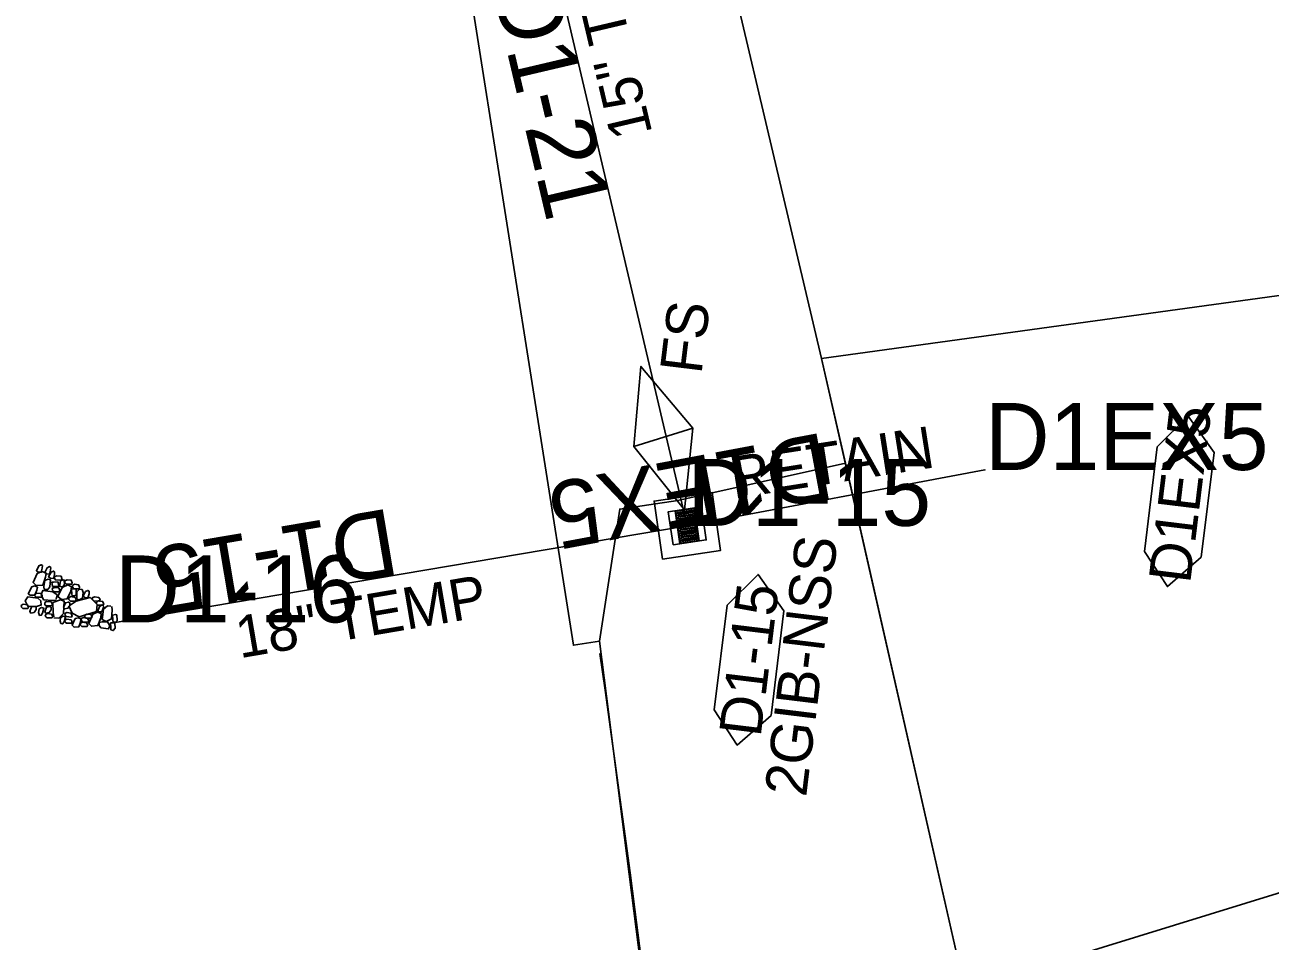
# Model space of a CAD drawing. Extents: x 465700 to 483515, y 488970 to 507540.
# Drawn here: x 481260.3 to 481409.1, y 491733.6 to 491843.1 of the extents above; entities that cross this region are included whole.
import ezdxf

# ---------------------------------------------------------------- set-up
doc = ezdxf.new("R2010")
doc.units = 0
for name, color, linetype in [('Default', 7, 'Continuous'), ('Exist Plan Preparation Watershed Blue', 7, 'Continuous'), ('Prop Drainage Structure Box Number Symbol CELL', 7, 'Continuous'), ('Prop Drainage Structure Drop Inlet Grate 2 Narrow Slots and Sag Grates 840 24 CELL', 7, 'Continuous'), ('Prop Drainage Structure Junction Box with Manhole Label', 7, 'Continuous'), ('Prop Drainage Structure Pipe Collar Label', 7, 'Continuous'), ('Prop Drainage Structure Pipe RCP 15in Class III', 7, 'Continuous'), ('Prop Drainage Structure Pipe RCP 15in Class III Label', 7, 'Continuous'), ('Prop Drainage Structure Pipe RCP 18in Class III', 7, 'Continuous'), ('Prop Drainage Structure Pipe RCP 18in Class III Label', 7, 'Continuous'), ('Prop Drainage Structure Pipe Stub Out CELL', 7, 'Continuous'), ('Prop Drainage Structure Plot Symbol 20 Scale CELL', 7, 'Continuous'), ('Prop Drainage Structure Plot Symbol 50 Scale CELL', 7, 'Continuous'), ('Prop Earthen Structure False Sump CELL', 7, 'Continuous'), ('Prop Earthen Structure False Sump Label', 7, 'Continuous'), ('Prop Erosion Rip Rap Pad at Outlet CELL', 7, 'Continuous'), ('Scratch_Level_8', 7, 'Continuous')]:
    doc.layers.add(name, color=color, linetype=linetype)

msp = doc.modelspace()

# ---------------------------------------------------------------- linework, layer by layer
at = {"layer": 'Default'}
msp.add_arc((478448.2, 491360.26), 2909.5, 356.95228, 8.055, dxfattribs=at)
at = {"layer": 'Exist Plan Preparation Watershed Blue'}
for points in [[(481914.1, 492508.16), (481856.26, 492637.66), (481730.25, 492750.66), (481730.25, 492750.66), (481669.43, 492692.33), (481584.65, 492614.4), (481584.65, 492614.4), (481584.65, 492614.4), (481329.7, 492355.65), (481209.8, 492230.86), (481241.6, 492138.31), (481300.91, 491917.87), (481327.1, 491923.15), (481339.19, 491872.39), (481355.48, 491803.22), (481355.48, 491803.22), (481355.48, 491803.22)], [(481355.48, 491803.22), (481621.38, 491839.87), (481663.65, 491819.01), (481786.78, 491759.9), (481848.66, 491780.37), (481859.12, 491782.21), (481859.12, 491782.21), (481859.12, 491782.21), (482127.99, 491863.91)], [(481351.25, 491164.11), (481355.63, 491237.92), (481357.02, 491295.88), (481357.71, 491377.55), (481356.61, 491435.42), (481354.34, 491495.85), (481349.13, 491584.55), (481341.19, 491673.05), (481328.95, 491769.45), (481331.36, 491785.24), (481338.28, 491786.26), (481358.32, 491790.73), (481372.6, 491727.76), (481383.56, 491677.38), (481390.7, 491636.27), (481400.08, 491578.77), (481407.45, 491514.97), (481410.05, 491479.29), (481411.52, 491442.54), (481412.58, 491412.05), (481413.67, 491377.22), (481412.27, 491323.04), (481409.74, 491273.14), (481400.35, 491179.93)], [(481400.08, 491578.77), (481390.7, 491636.27), (481383.56, 491677.38), (481376.93, 491707.39), (481374.23, 491721.13), (481372.6, 491727.76), (481418.44, 491741.89), (481486.66, 491760.25), (481538.81, 491759.7), (481786.78, 491759.9), (481786.78, 491759.9), (481786.78, 491759.9), (481786.78, 491759.9), (481786.78, 491759.9), (481786.78, 491759.9), (481786.78, 491759.9), (481786.78, 491759.9), (481786.78, 491759.9), (481568.07, 491531.08)]]:
    msp.add_lwpolyline(points, dxfattribs=at)
for points in [[(481328.95, 491769.45), (481325.82, 491768.95), (481313.54, 491846.95), (481303.37, 491904.07), (481300.91, 491917.87), (481304.12, 491918.69), (481311, 491920.02), (481327.1, 491923.15), (481339.19, 491872.39), (481355.48, 491803.22), (481358.32, 491790.73), (481338.28, 491786.26), (481331.36, 491785.24)], [(481372.6, 491727.76), (481418.44, 491741.89), (481486.66, 491760.25), (481538.81, 491759.7), (481786.78, 491759.9), (481720.28, 491792.68), (481663.65, 491819.01), (481642.72, 491828.88), (481621.38, 491839.87), (481355.48, 491803.22)]]:
    msp.add_lwpolyline(points, close=True, dxfattribs=at)
at = {"layer": 'Prop Drainage Structure Box Number Symbol CELL'}
for points in [[(481394.05, 491780.17), (481395.57, 491792.68), (481399.28, 491796.36), (481402.36, 491792.01), (481400.83, 491779.5), (481396.79, 491775.97), (481394.05, 491780.17)], [(481342.65, 491761.22), (481344.18, 491773.74), (481347.88, 491777.42), (481350.96, 491773.07), (481349.43, 491760.56), (481345.39, 491757.02), (481342.65, 491761.22)]]:
    msp.add_lwpolyline(points, dxfattribs=at)
at = {"layer": 'Prop Drainage Structure Drop Inlet Grate 2 Narrow Slots and Sag Grates 840 24 CELL'}
for p, q in [((481339.13, 491785.21), (481339.13, 491785.21)), ((481338.27, 491783.06), (481338.27, 491783.06)), ((481339.42, 491783.23), (481339.42, 491783.23)), ((481340.57, 491783.4), (481340.57, 491783.4)), ((481339.71, 491781.25), (481339.71, 491781.25))]:
    msp.add_line(p, q, dxfattribs=at)
for points in [[(481338.55, 491781.08), (481337.98, 491785.04), (481340.28, 491785.38), (481340.86, 491781.42), (481338.55, 491781.08)], [(481338.61, 491781.15), (481338.05, 491784.99), (481340.23, 491785.31), (481340.79, 491781.47), (481338.61, 491781.15)], [(481338.34, 491783.08), (481338.06, 491784.98), (481340.22, 491785.3), (481340.5, 491783.4), (481338.34, 491783.08)], [(481338.29, 491784.67), (481338.26, 491784.84), (481340.07, 491785.1), (481340.09, 491784.93), (481338.29, 491784.67)], [(481338.33, 491784.37), (481338.31, 491784.55), (481340.11, 491784.81), (481340.14, 491784.64), (481338.33, 491784.37)], [(481338.37, 491784.08), (481338.35, 491784.25), (481340.15, 491784.52), (481340.18, 491784.34), (481338.37, 491784.08)], [(481338.62, 491781.17), (481338.34, 491783.06), (481340.5, 491783.38), (481340.78, 491781.48), (481338.62, 491781.17)], [(481338.42, 491783.78), (481338.39, 491783.96), (481340.2, 491784.22), (481340.22, 491784.05), (481338.42, 491783.78)], [(481338.46, 491783.49), (481338.43, 491783.67), (481340.24, 491783.93), (481340.26, 491783.75), (481338.46, 491783.49)], [(481338.5, 491783.2), (481338.48, 491783.37), (481340.28, 491783.64), (481340.31, 491783.46), (481338.5, 491783.2)], [(481338.56, 491782.83), (481338.53, 491783), (481340.34, 491783.26), (481340.36, 491783.09), (481338.56, 491782.83)], [(481338.6, 491782.53), (481338.58, 491782.71), (481340.38, 491782.97), (481340.4, 491782.8), (481338.6, 491782.53)], [(481338.64, 491782.24), (481338.62, 491782.41), (481340.42, 491782.68), (481340.45, 491782.5), (481338.64, 491782.24)], [(481338.69, 491781.94), (481338.66, 491782.12), (481340.46, 491782.38), (481340.49, 491782.21), (481338.69, 491781.94)], [(481338.73, 491781.65), (481338.7, 491781.83), (481340.51, 491782.09), (481340.53, 491781.91), (481338.73, 491781.65)], [(481338.77, 491781.36), (481338.75, 491781.53), (481340.55, 491781.8), (481340.58, 491781.62), (481338.77, 491781.36)]]:
    msp.add_lwpolyline(points, dxfattribs=at)
at = {"layer": 'Prop Drainage Structure Pipe RCP 15in Class III'}
msp.add_line((481308.23, 491915.92), (481339.42, 491783.23), dxfattribs=at)
at = {"layer": 'Prop Drainage Structure Pipe RCP 18in Class III'}
msp.add_line((481339.42, 491783.23), (481271.07, 491771.69), dxfattribs=at)
at = {"layer": 'Prop Drainage Structure Pipe Stub Out CELL'}
msp.add_line((481374.98, 491789.91), (481374.98, 491789.91), dxfattribs=at)
msp.add_line((481374.98, 491789.91), (481374.98, 491789.91), dxfattribs=at)
msp.add_lwpolyline([(481374.96, 491789.9), (481374.98, 491789.92), (481375, 491789.91), (481374.98, 491789.89), (481374.96, 491789.9)], dxfattribs=at)
at = {"layer": 'Prop Drainage Structure Plot Symbol 20 Scale CELL'}
msp.add_lwpolyline([(481337.73, 491780.96), (481337.15, 491784.92), (481341.11, 491785.5), (481341.69, 491781.54)], close=True, dxfattribs=at)
at = {"layer": 'Prop Drainage Structure Plot Symbol 50 Scale CELL'}
msp.add_lwpolyline([(481336.46, 491779.26), (481335.45, 491786.19), (481342.38, 491787.2), (481343.39, 491780.27)], close=True, dxfattribs=at)
at = {"layer": 'Prop Earthen Structure False Sump CELL'}
msp.add_lwpolyline([(481339.11, 491785.14), (481333.04, 491792.71), (481333.89, 491802.29), (481340.07, 491794.92), (481333.04, 491792.71), (481340.07, 491794.92), (481339.11, 491785.14)], dxfattribs=at)
at = {"layer": 'Prop Erosion Rip Rap Pad at Outlet CELL'}
msp.add_line((481271.07, 491771.69), (481271.07, 491771.69), dxfattribs=at)
msp.add_line((481271.07, 491771.69), (481271.07, 491771.69), dxfattribs=at)
for points in [[(481262.4, 491778.48), (481262.37, 491778.16), (481262.24, 491777.69), (481261.88, 491777.71), (481261.66, 491777.87), (481261.95, 491778.44), (481262.23, 491778.57), (481262.4, 491778.48)], [(481262.84, 491777.59), (481262.73, 491777.08), (481262.42, 491776.15), (481261.63, 491776.08), (481261.26, 491776.45), (481261.75, 491777.55), (481262.35, 491777.77), (481262.84, 491777.59)], [(481263.39, 491778.26), (481263.36, 491777.95), (481263.23, 491777.47), (481262.87, 491777.49), (481262.65, 491777.65), (481262.94, 491778.22), (481263.22, 491778.35), (481263.39, 491778.26)], [(481263.84, 491777.74), (481263.82, 491777.42), (481263.69, 491776.95), (481263.34, 491776.97), (481263.11, 491777.13), (481263.41, 491777.7), (481263.69, 491777.83), (481263.84, 491777.74)], [(481263.8, 491777.15), (481264.11, 491777.24), (481264.62, 491777.2), (481264.71, 491776.92), (481264.65, 491776.76), (481264, 491776.75), (481263.83, 491776.94), (481263.8, 491777.15)], [(481261.78, 491775.9), (481261.71, 491775.53), (481261.49, 491774.94), (481260.92, 491774.93), (481260.68, 491775.11), (481261.11, 491775.95), (481261.48, 491776.06), (481261.78, 491775.9)], [(481262.58, 491775.61), (481262.53, 491775.99), (481262.66, 491776.7), (481263.05, 491776.87), (481263.33, 491776.76), (481263.25, 491775.92), (481263.02, 491775.61), (481262.58, 491775.61)], [(481263.51, 491776.5), (481263.71, 491776.5), (481264.24, 491776.52), (481264.35, 491776.15), (481264.28, 491775.98), (481263.6, 491775.99), (481263.53, 491776.25), (481263.51, 491776.5)], [(481263.55, 491775.73), (481263.84, 491775.87), (481264.33, 491775.8), (481264.46, 491775.5), (481264.37, 491775.34), (481263.77, 491775.36), (481263.59, 491775.51), (481263.55, 491775.73)], [(481265.87, 491775.95), (481265.78, 491775.42), (481265.34, 491774.51), (481264.67, 491774.44), (481264.24, 491774.78), (481264.75, 491775.87), (481265.4, 491776.19), (481265.87, 491775.95)], [(481264.47, 491775.93), (481264.48, 491776.16), (481264.55, 491776.65), (481264.83, 491776.78), (481264.98, 491776.74), (481265.02, 491776.2), (481264.8, 491775.96), (481264.59, 491775.92)], [(481265.07, 491776.64), (481265.32, 491776.79), (481265.82, 491776.72), (481265.95, 491776.43), (481265.88, 491776.26), (481265.24, 491776.25), (481265.07, 491776.44), (481265.07, 491776.64)], [(481265.92, 491774.87), (481265.89, 491775.11), (481265.87, 491775.64), (481266.25, 491775.71), (481266.4, 491775.65), (481266.4, 491775), (481266.24, 491774.86), (481265.92, 491774.87)], [(481265.96, 491776.09), (481266.2, 491776.24), (481266.7, 491776.17), (481266.83, 491775.88), (481266.76, 491775.7), (481266.13, 491775.7), (481265.96, 491775.89), (481265.96, 491776.09)], [(481267.13, 491775.62), (481267.23, 491775.27), (481267.18, 491774.57), (481266.78, 491774.37), (481266.5, 491774.48), (481266.5, 491775.35), (481266.81, 491775.64), (481267.13, 491775.62)], [(481262.16, 491773.73), (481261.68, 491773.58), (481260.65, 491773.64), (481260.33, 491774.28), (481260.63, 491774.73), (481261.85, 491774.6), (481262.2, 491774.26), (481262.23, 491773.7)], [(481261.47, 491775.06), (481261.73, 491775.2), (481262.23, 491775.15), (481262.36, 491774.86), (481262.29, 491774.69), (481261.64, 491774.69), (481261.47, 491774.86), (481261.47, 491775.06)], [(481264.02, 491774.34), (481263.58, 491774.32), (481262.52, 491774.39), (481262.25, 491775.01), (481262.43, 491775.5), (481263.64, 491775.33), (481264.16, 491774.98), (481264.03, 491774.46)], [(481262.66, 491774.05), (481262.88, 491774.17), (481263.44, 491774.13), (481263.57, 491773.84), (481263.46, 491773.68), (481262.83, 491773.68), (481262.68, 491773.8), (481262.66, 491774.05)], [(481263.76, 491772.34), (481263.68, 491772.87), (481263.64, 491774.05), (481264.53, 491774.4), (481264.99, 491774.23), (481264.88, 491772.75), (481264.36, 491772.19), (481263.73, 491772.22)], [(481265.67, 491774.04), (481265.67, 491773.72), (481265.43, 491773.37), (481265.04, 491773.31), (481264.91, 491773.48), (481265.12, 491774.04), (481265.49, 491774.11), (481265.67, 491774.04)], [(481265.69, 491773.73), (481266.4, 491774.22), (481268.07, 491774.68), (481268.91, 491773.81), (481268.85, 491772.99), (481266.79, 491772.36), (481265.92, 491772.81), (481265.53, 491773.68)], [(481265.55, 491774.63), (481265.78, 491774.77), (481266.28, 491774.67), (481266.42, 491774.43), (481266.34, 491774.22), (481265.72, 491774.24), (481265.55, 491774.42), (481265.55, 491774.63)], [(481267.98, 491775.42), (481267.95, 491775.11), (481267.81, 491774.64), (481267.46, 491774.66), (481267.24, 491774.81), (481267.53, 491775.38), (481267.81, 491775.51), (481267.98, 491775.42)], [(481268.34, 491774.64), (481268.62, 491774.75), (481269.12, 491774.68), (481269.26, 491774.43), (481269.18, 491774.22), (481268.53, 491774.26), (481268.38, 491774.43), (481268.34, 491774.64)], [(481268.83, 491774.11), (481269.08, 491774.26), (481269.57, 491774.19), (481269.7, 491773.9), (481269.63, 491773.73), (481269, 491773.74), (481268.83, 491773.91), (481268.83, 491774.11)], [(481259.85, 491773.72), (481260.1, 491773.88), (481260.59, 491773.8), (481260.73, 491773.52), (481260.63, 491773.35), (481260.04, 491773.36), (481259.89, 491773.5), (481259.85, 491773.72)], [(481261.64, 491773.53), (481261.64, 491773.21), (481261.39, 491772.86), (481261.01, 491772.81), (481260.87, 491772.99), (481261.08, 491773.55), (481261.47, 491773.6), (481261.64, 491773.53)], [(481262.04, 491772.53), (481261.92, 491772.85), (481262, 491773.29), (481262.27, 491773.48), (481262.55, 491773.38), (481262.41, 491772.79), (481262.24, 491772.54), (481262.04, 491772.53)], [(481263.43, 491773.52), (481263.43, 491773.19), (481263.19, 491772.85), (481262.8, 491772.79), (481262.67, 491772.96), (481262.88, 491773.52), (481263.25, 491773.59), (481263.43, 491773.52)], [(481262.72, 491772.59), (481262.97, 491772.75), (481263.47, 491772.67), (481263.61, 491772.4), (481263.51, 491772.24), (481262.92, 491772.24), (481262.77, 491772.37), (481262.72, 491772.59)], [(481265.05, 491772.77), (481265.3, 491772.88), (481265.77, 491772.79), (481265.92, 491772.53), (481265.84, 491772.32), (481265.22, 491772.38), (481265.09, 491772.55), (481265.05, 491772.77)], [(481267.43, 491772.55), (481267.67, 491772.69), (481268.17, 491772.62), (481268.31, 491772.34), (481268.21, 491772.18), (481267.61, 491772.19), (481267.46, 491772.33), (481267.43, 491772.55)], [(481269.41, 491772.75), (481269.34, 491772.25), (481268.99, 491771.3), (481268.23, 491771.22), (481267.91, 491771.54), (481268.42, 491772.68), (481268.95, 491772.91), (481269.41, 491772.75)], [(481269.71, 491773.6), (481269.64, 491773.39), (481269.49, 491772.96), (481269.16, 491772.96), (481268.99, 491773.03), (481269.2, 491773.59), (481269.51, 491773.79), (481269.71, 491773.6)], [(481270.68, 491773.59), (481270.71, 491773.15), (481270.65, 491772.12), (481270.01, 491771.8), (481269.52, 491772.03), (481269.67, 491773.25), (481270.15, 491773.68), (481270.56, 491773.64)], [(481270.79, 491771.8), (481270.8, 491772.03), (481270.76, 491772.57), (481271.1, 491772.65), (481271.27, 491772.58), (481271.32, 491771.91), (481271.07, 491771.69), (481270.79, 491771.8)], [(481264.6, 491771.57), (481264.5, 491771.82), (481264.53, 491772.24), (481264.82, 491772.45), (481265.13, 491772.35), (481264.98, 491771.76), (481264.78, 491771.51), (481264.6, 491771.57)], [(481265.05, 491771.95), (481265.3, 491772.09), (481265.8, 491772.01), (481265.93, 491771.74), (481265.83, 491771.58), (481265.24, 491771.59), (481265.09, 491771.73), (481265.05, 491771.95)], [(481266.96, 491772.13), (481266.93, 491771.71), (481266.72, 491771.15), (481266.16, 491771.11), (481265.92, 491771.37), (481266.31, 491772.14), (481266.69, 491772.23), (481266.96, 491772.13)], [(481266.91, 491771.55), (481267.16, 491771.71), (481267.65, 491771.63), (481267.8, 491771.35), (481267.69, 491771.19), (481267.1, 491771.21), (481266.94, 491771.34), (481266.91, 491771.55)], [(481266.99, 491772.14), (481267.29, 491772.27), (481267.76, 491772.16), (481267.91, 491771.91), (481267.83, 491771.7), (481267.16, 491771.75), (481267.03, 491771.92), (481266.99, 491772.14)], [(481269.17, 491771.69), (481269.52, 491771.75), (481270.15, 491771.76), (481270.42, 491771.29), (481270.29, 491770.91), (481269.37, 491771.05), (481269.16, 491771.33), (481269.17, 491771.69)], [(481270.55, 491770.8), (481270.55, 491771.05), (481270.53, 491771.62), (481270.86, 491771.65), (481271.04, 491771.59), (481271.07, 491770.98), (481270.84, 491770.7), (481270.55, 491770.8)]]:
    msp.add_lwpolyline(points, dxfattribs=at)
at = {"layer": 'Scratch_Level_8'}
for p, q in [((481308.23, 491915.92), (481339.42, 491783.23)), ((481374.98, 491789.91), (481339.42, 491783.23)), ((481339.42, 491783.23), (481271.07, 491771.69))]:
    msp.add_line(p, q, dxfattribs=at)

# ---------------------------------------------------------------- texts
at = {"layer": 'Prop Drainage Structure Box Number Symbol CELL'}
for s, p in [('D1EX5', (481399.5, 491776.24)), ('D1-15', (481348.18, 491757.89))]:
    msp.add_text(s, height=5, rotation=83.0394, dxfattribs=at).set_placement(p)
at = {"layer": 'Prop Drainage Structure Junction Box with Manhole Label'}
msp.add_text('2GIB-NSS', height=5, rotation=83.0365, dxfattribs=at).set_placement((481353.62, 491750.73))
at = {"layer": 'Prop Drainage Structure Pipe Collar Label'}
msp.add_text('RETAIN', height=5, rotation=8.9195, dxfattribs=at).set_placement((481344.96, 491786.45))
at = {"layer": 'Prop Drainage Structure Pipe RCP 15in Class III Label'}
msp.add_text('15" TEMP', height=5, rotation=103.2285, dxfattribs=at).set_placement((481335.27, 491830.17))
at = {"layer": 'Prop Drainage Structure Pipe RCP 18in Class III Label'}
msp.add_text('18" TEMP', height=5, rotation=9.7092, dxfattribs=at).set_placement((481285.95, 491767.39))
at = {"layer": 'Prop Drainage Structure Pipe Stub Out CELL'}
msp.add_text('SO', height=0.0104, rotation=12.9811, dxfattribs=at).set_placement((481374.97, 491789.9))
at = {"layer": 'Prop Earthen Structure False Sump Label'}
msp.add_text('FS', height=5, rotation=83.0423, dxfattribs=at).set_placement((481341.11, 491801.27))
at = {"layer": 'Scratch_Level_8'}
for s, rotation, p in [('D1-21', 283.2285, (481316.04, 491847.75)), ('D1EX5', 190.632, (481355.72, 491794.43)), ('D1-15', 189.5858, (481303.91, 491785.35))]:
    msp.add_text(s, height=8, rotation=rotation, dxfattribs=at).set_placement(p)
for s, p in [('D1EX5', (481374.98, 491789.91)), ('D1-15', (481339.42, 491783.23)), ('D1-16', (481271.07, 491771.69))]:
    msp.add_text(s, height=8, dxfattribs=at).set_placement(p)

doc.saveas('drawing.dxf')
